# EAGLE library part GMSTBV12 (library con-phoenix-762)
PHOENIX
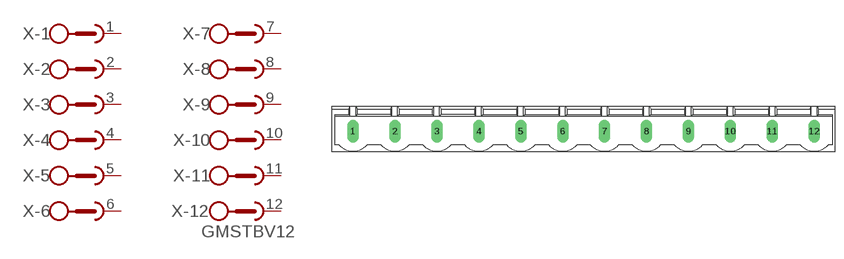
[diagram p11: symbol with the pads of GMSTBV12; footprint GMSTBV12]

Designator prefix X; gates -1=SKB -2=SKB -3=SKB -4=SKB -5=SKB -6=SKB -7=SKB -8=SKB -9=SKB -10=SKB -11=SKB -12=SKBV

## GMSTBV12 (OC_FARNELL: unknown; OC_NEWARK: unknown)  [GMSTBV12]
1  -1:1  pas
2  -2:1  pas
3  -3:1  pas
4  -4:1  pas
5  -5:1  pas
6  -6:1  pas
7  -7:1  pas
8  -8:1  pas
9  -9:1  pas
10  -10:1  pas
11  -11:1  pas
12  -12:1  pas

## Footprint GMSTBV12 (pad centres in mm)
PHOENIX
drill 1.397 long: 1 -41.91,0; 2 -34.29,0; 3 -26.67,0; 4 -19.05,0; 5 -11.43,0; 6 -3.81,0; 7 3.81,0; 8 11.43,0; 9 19.05,0; 10 26.67,0; 11 34.29,0; 12 41.91,0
